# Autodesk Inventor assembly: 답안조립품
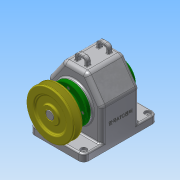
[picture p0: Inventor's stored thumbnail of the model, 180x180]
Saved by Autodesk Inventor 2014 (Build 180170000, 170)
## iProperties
Created: 2016-12
Part Number: 답안조립품
Document SubType Name: Assembly
Designer: net
Author: net
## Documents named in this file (15)
- C:\Users\net\Desktop\461207V1010\답안조립품.iam
- C:\Users\net\Desktop\461207V1010\본체.ipt
- C:\Users\net\Desktop\461207V1010\V-벨트풀리.ipt
- C:\Users\net\Desktop\461207V1010\뒤커버.ipt
- C:\Users\net\Desktop\461207V1010\멈춤나사 - M4x10.ipt
- C:\Users\net\Desktop\461207V1010\베어링 6203.ipt
- C:\Users\net\Desktop\461207V1010\볼트 M3 x 8.ipt
- C:\Users\net\Desktop\461207V1010\볼트 M3 x 10.ipt
- C:\Users\net\Desktop\461207V1010\부시.ipt
- C:\Users\net\Desktop\461207V1010\스퍼기어.ipt
- C:\Users\net\Desktop\461207V1010\앞커버.ipt
- C:\Users\net\Desktop\461207V1010\오일씰 28 40 8.ipt
- C:\Users\net\Desktop\461207V1010\축.ipt
- C:\Users\net\Desktop\461207V1010\키 - 5 x 5 x 18.ipt
- C:\Users\net\Desktop\461207V1010\키 - 6 x 6 x 22.ipt
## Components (9 placed, 3 different names)
1. V-벨트풀리:1 — 각도:4
2. ISO 4762 M3 x 10:1
3. ISO 4762 M3 x 10:2
4. ISO 4762 M3 x 10:3
5. ISO 4762 M3 x 10:4
6. ISO 4762 M3 x 8:1
7. ISO 4762 M3 x 8:2
8. ISO 4762 M3 x 8:3
9. ISO 4762 M3 x 8:4
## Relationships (1: Angle 1)
- 각도:4 [Angle]: V-벨트풀리:1
